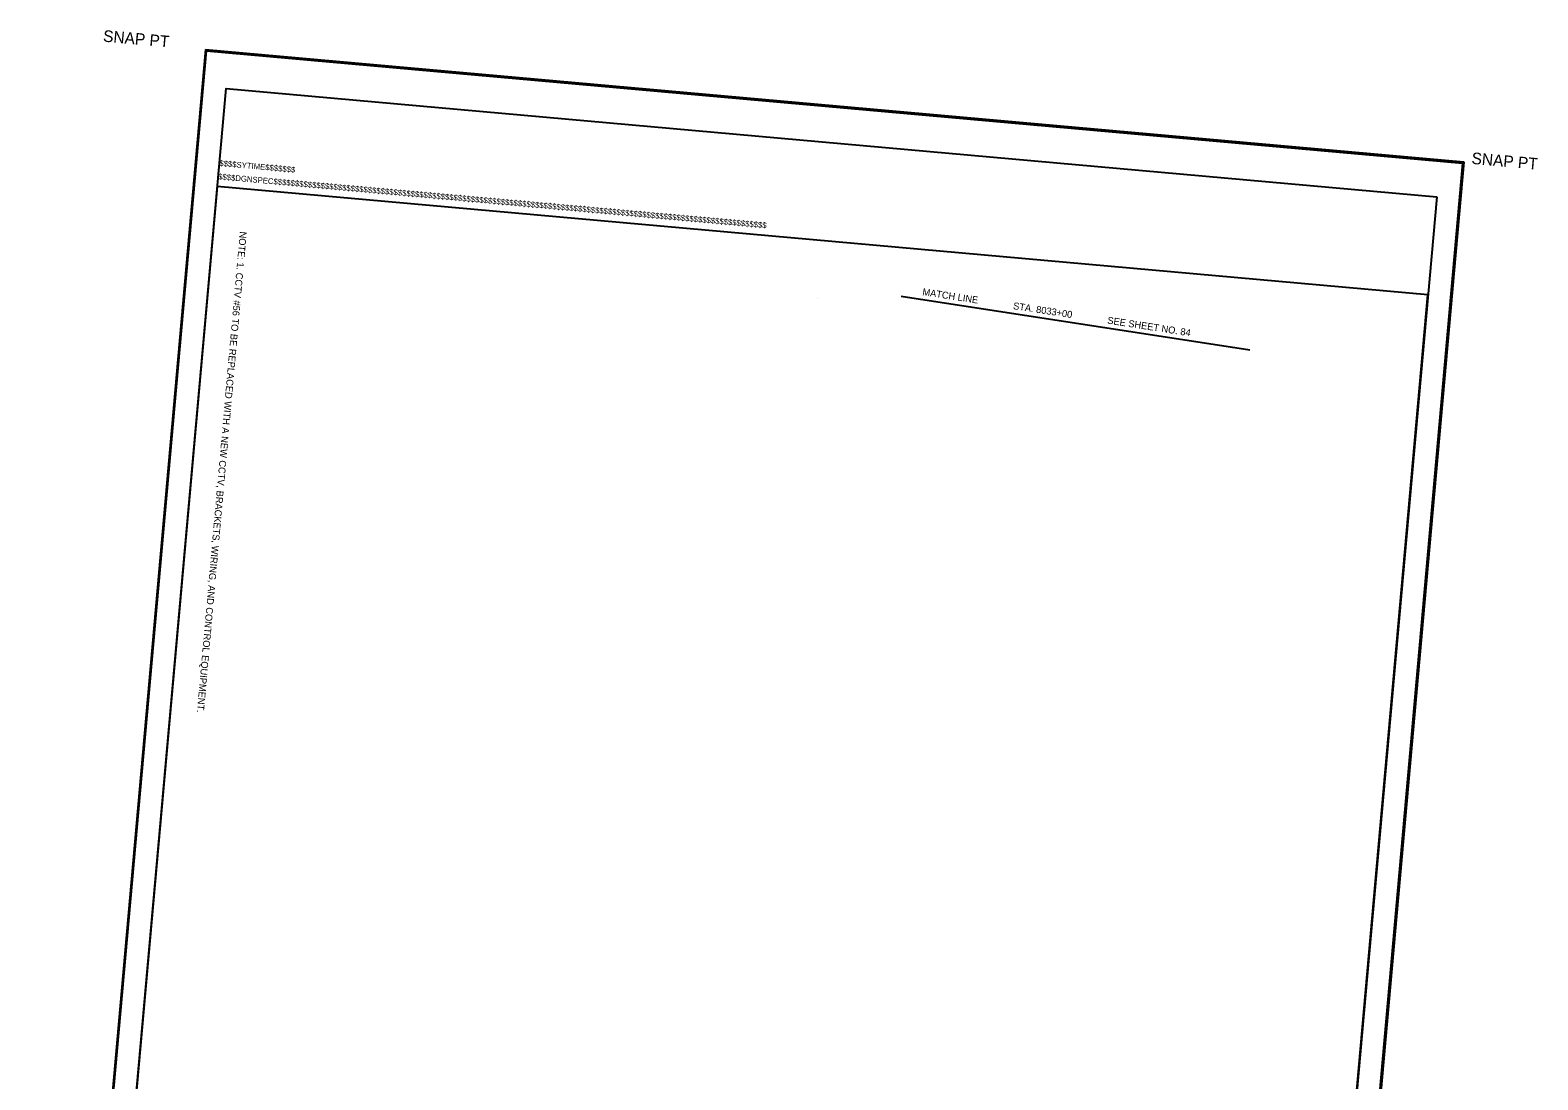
# Model space of a CAD drawing. Extents: x 1751939 to 1754719, y 651993 to 655620.
# Drawn here: x 1752115 to 1754719, y 653806 to 655620 of the extents above; entities that cross this region are included whole.
import ezdxf

# ---------------------------------------------------------------- set-up
doc = ezdxf.new("R2010")
doc.units = 0
for name, color, linetype in [('DESIGN - SCRATCH - User 1', 7, 'Continuous'), ('DESIGN - SHEET - Corner Text', 7, 'Continuous'), ('DESIGN - SHEET - Linework', 7, 'Continuous'), ('DESIGN - SHEET - Plot Shape', 7, 'Continuous'), ('ITS - EXISTING CCTV TEXT', 7, 'Continuous'), ('ITS - EXISTING COMM CABLE', 7, 'Continuous')]:
    doc.layers.add(name, color=color, linetype=linetype)

msp = doc.modelspace()

# ---------------------------------------------------------------- linework, layer by layer
at = {"layer": 'DESIGN - SCRATCH - User 1'}
msp.add_line((1753474.9, 655156.5), (1753474.9, 655156.5), dxfattribs=at)
at = {"layer": 'DESIGN - SHEET - Linework'}
for p, q in [((1752417.5, 655586.2), (1752114.6, 652195.7)), ((1752417.5, 655586.2), (1754591.7, 655392)), ((1754591.7, 655392), (1754288.8, 652001.5))]:
    msp.add_line(p, q, dxfattribs=at)
msp.add_lwpolyline([(1754529.6, 655162.7), (1752438, 655349.6), (1752157.8, 652213.7), (1754249.5, 652026.8), (1754529.6, 655162.7)], dxfattribs=at)
at = {"layer": 'DESIGN - SHEET - Plot Shape'}
for points in [[(1754589.5, 655390.2), (1754287, 652003.7), (1752116.8, 652197.5), (1752419.4, 655584.1)], [(1754544.8, 655332.1), (1754249.5, 652026.8), (1752157.8, 652213.7), (1752453.1, 655519)]]:
    msp.add_lwpolyline(points, close=True, dxfattribs=at)
at = {"layer": 'ITS - EXISTING COMM CABLE'}
msp.add_line((1753619.7, 655160), (1754221.8, 655067.3), dxfattribs=at)

# ---------------------------------------------------------------- texts
at = {"layer": 'DESIGN - SHEET - Corner Text'}
for s, height, p in [('SNAP PT  ', 20, (1752240.1, 655600.1)), ('  SNAP PT', 20, (1754589.5, 655390.2)), ('$$$$SYTIME$$$$$$$', 10, (1752441.2, 655385.2)), ('$$$$DGNSPEC$$$$$$$$$$$$$$$$$$$$$$$$$$$$$$$$$$$$$$$$$$$$$$$$$$$$$$$$$$$$$$$$$$$$$$$$$$$$$$$$$$$$$$$$$$$$$$$$$$$$$$$$$$$$$$$$$$$', 10.0002, (1752439.1, 655362.1))]:
    msp.add_text(s, height=height, rotation=354.8949, dxfattribs=at).set_placement(p)
at = {"layer": 'ITS - EXISTING CCTV TEXT'}
msp.add_text('NOTE: 1. CCTV #56 TO BE REPLACED WITH A NEW CCTV, BRACKETS, WIRING, AND CONTROL EQUIPMENT.', height=12, rotation=264.8948, dxfattribs=at).set_placement((1752477, 655272.3))
at = {"layer": 'ITS - EXISTING COMM CABLE'}
for s, p in [('MATCH LINE', (1753655.6, 655162.1)), ('STA. 8033+00', (1753812.3, 655137.9)), ('SEE SHEET NO. 84 ', (1753975.1, 655112.9))]:
    msp.add_text(s, height=12, rotation=351.2479, dxfattribs=at).set_placement(p)

doc.saveas('drawing.dxf')
